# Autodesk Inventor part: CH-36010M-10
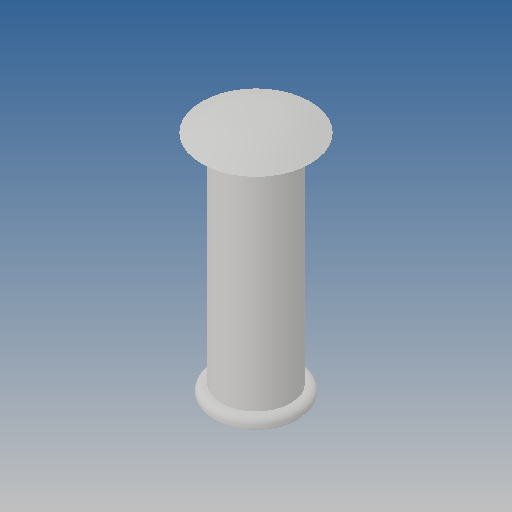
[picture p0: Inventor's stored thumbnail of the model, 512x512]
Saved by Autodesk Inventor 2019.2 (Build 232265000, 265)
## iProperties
Created: 2012-09
Part Number: CH-36010M-10
Material: Ogólny
Document SubType Name: Modeling
Designer: CADENGINEERING4
Density: 1 g/cm^3
Appearance: Domyślna
Author: CADENGINEERING4
Revision Number: ÈÎºÎ
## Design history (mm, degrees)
feature "Ô²½Ç2"
node "Bryła1"
